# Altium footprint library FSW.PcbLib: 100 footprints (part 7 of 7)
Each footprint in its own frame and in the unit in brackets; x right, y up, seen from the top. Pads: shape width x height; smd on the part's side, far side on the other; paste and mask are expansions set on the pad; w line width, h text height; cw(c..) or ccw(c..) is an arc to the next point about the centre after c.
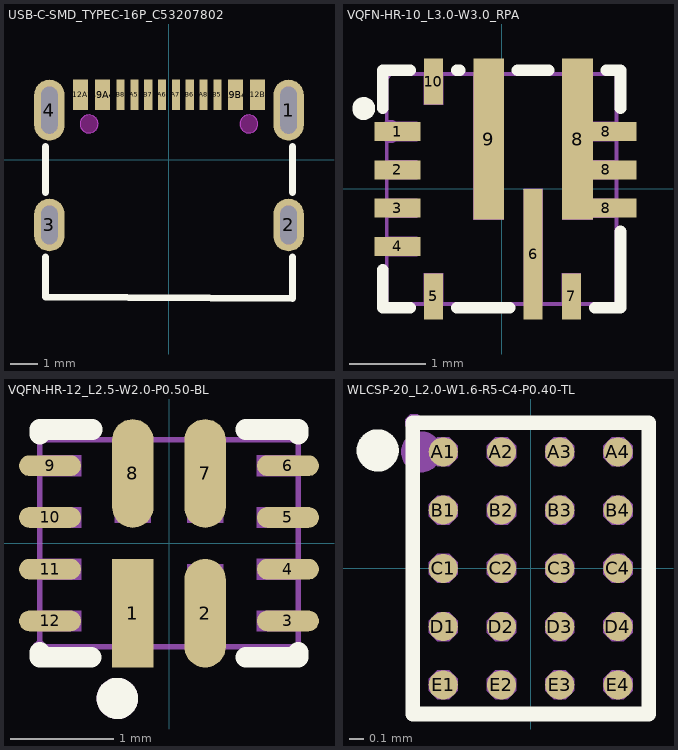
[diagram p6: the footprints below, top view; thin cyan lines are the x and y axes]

## USB-C-SMD_TYPEC-16P_C53207802 [mm]
pads (16):
  oval 1.1x2.2 hole 0.6 slot 1.7 at 90 deg copper offset 0,0 paste-2539.97 mask+0.05: 1(4.32,1.8)
  oval 1.1x1.9 hole 0.6 slot 1.4 at 90 deg copper offset 0,0 paste-2539.97 mask+0.05: 2(4.32,-2.35)
  oval 1.1x1.9 hole 0.6 slot 1.4 at 90 deg paste-2539.97 mask+0.05: 3(-4.32,-2.35)
  oval 1.1x2.2 hole 0.6 slot 1.7 at 90 deg paste-2539.97 mask+0.05: 4(-4.32,1.8)
  rect 0.3x1.1 smd paste+0 mask+0.05: A5(-1.25,2.35) A6(-0.25,2.35) A7(0.25,2.35) A8(1.25,2.35) B5(1.75,2.35) B6(0.75,2.35) B7(-0.75,2.35) B8(-1.75,2.35)
  rect 0.55x1.1 smd paste+0 mask+0.05: A9B4(2.4,2.35) A12B1(3.2,2.35) B9A4(-2.4,2.35) B12A1(-3.2,2.35)
Top Overlay:
  lines w0.254: -4.47,-3.517 -4.47,-4.951 4.47,-5.001 4.47,-3.517 ; -4.47,-1.183 -4.47,0.484 ; 4.47,-1.183 4.47,0.484
Keep-Out Layer:
  board cut-out: 3.215,1.3 3.215,1.235 3.166,1.116 3.074,1.024 2.955,0.975 2.825,0.975 2.706,1.024 2.615,1.116 2.565,1.235 2.565,1.3 2.565,1.365 2.615,1.484 2.706,1.575 2.825,1.625 2.955,1.625 3.074,1.575 3.166,1.484 3.215,1.365 3.215,1.3
  board cut-out: -2.565,1.3 -2.565,1.235 -2.614,1.116 -2.706,1.024 -2.825,0.975 -2.955,0.975 -3.074,1.024 -3.165,1.116 -3.215,1.235 -3.215,1.3 -3.215,1.365 -3.165,1.484 -3.074,1.575 -2.955,1.625 -2.825,1.625 -2.706,1.575 -2.614,1.484 -2.565,1.365 -2.565,1.3
Keep-Out Layer:
  circle w0.003: c2.89,1.3 r0.325
  circle w0.003: c-2.89,1.3 r0.325
  region: 3.215,1.3 3.206,1.222 3.178,1.149 3.133,1.084 3.075,1.032 3.005,0.996 2.929,0.977 2.851,0.977 2.775,0.996 2.706,1.032 2.647,1.084 2.602,1.149 2.575,1.222 2.565,1.3 2.575,1.378 2.602,1.451 2.647,1.515 2.706,1.567 2.775,1.604 2.851,1.623 2.929,1.623 3.005,1.604 3.075,1.567 3.133,1.515 3.178,1.451 3.206,1.378
  region: 3.215,1.3 3.215,1.235 3.166,1.116 3.074,1.024 2.955,0.975 2.825,0.975 2.706,1.024 2.615,1.116 2.565,1.235 2.565,1.3 2.565,1.365 2.615,1.484 2.706,1.575 2.825,1.625 2.955,1.625 3.074,1.575 3.166,1.484 3.215,1.365 3.215,1.3
  region: -2.565,1.3 -2.574,1.222 -2.602,1.149 -2.647,1.084 -2.705,1.032 -2.775,0.996 -2.851,0.977 -2.929,0.977 -3.005,0.996 -3.075,1.032 -3.133,1.084 -3.178,1.149 -3.205,1.222 -3.215,1.3 -3.205,1.378 -3.178,1.451 -3.133,1.515 -3.075,1.567 -3.005,1.604 -2.929,1.623 -2.851,1.623 -2.775,1.604 -2.705,1.567 -2.647,1.515 -2.602,1.451 -2.574,1.378
  region: -2.565,1.3 -2.565,1.235 -2.614,1.116 -2.706,1.024 -2.825,0.975 -2.955,0.975 -3.074,1.024 -3.165,1.116 -3.215,1.235 -3.215,1.3 -3.215,1.365 -3.165,1.484 -3.074,1.575 -2.955,1.625 -2.825,1.625 -2.706,1.575 -2.614,1.484 -2.565,1.365 -2.565,1.3
Mechanical 1:
  circle w0.003: c2.89,1.3 r0.325
  circle w0.003: c-2.89,1.3 r0.325
3D body "USB-C-SMD_TYPE-C-16PIN-2MD-073.step": height 3.36, standoff -0.8, extent -4.343,-4.935 4.597,2.645

## VQFN-HR-10_L3.0-W3.0_RPA [mm]
pads (13):
  rect 0.6x0.25 smd paste-100 mask+0.05: 1(-1.36,0.75) 2(-1.36,0.25) 3(-1.36,-0.25) 4(-1.36,-0.75)
  rect 0.25x0.6 smd paste-100 mask+0.05: 5(-0.89,-1.4) 7(0.91,-1.4) 10(-0.89,1.4)
  rect 0.25x1.7 smd paste-100 mask+0.05: 6(0.41,-0.85)
  rect 0.4x2.1 smd paste-100 mask+0.05: 8(0.99,0.65) 9(-0.17,0.65)
  rect 0.8x0.25 smd paste-100 mask+0.05: 8(1.36,-0.25) 8(1.36,0.25) 8(1.36,0.75)
Top Overlay:
  circle w0.15: c-1.8,1.05 r0.075
  lines w0.152: -1.55,-1.055 -1.55,-1.55 -1.195,-1.55 ; -1.55,1.055 -1.55,1.55 -1.195,1.55 ; -0.585,-1.55 0.105,-1.55 ; -0.585,1.55 -0.547,1.55 ; 0.207,1.55 0.613,1.55 ; 1.215,-1.55 1.55,-1.55 1.55,-0.555 ; 1.367,1.55 1.55,1.55 1.55,1.055
Top Paste:
  region: 0.285,-1.699 0.535,-1.699 0.535,0 0.285,0 0.285,-0.699
  region: -0.765,1.7 -1.015,1.7 -1.015,1.1 -0.765,1.1 -0.765,1.177
  region: -1.06,0.625 -1.06,0.875 -1.66,0.875 -1.66,0.625 -1.583,0.625
  region: -1.06,0.125 -1.06,0.375 -1.66,0.375 -1.66,0.125 -1.583,0.125
  region: -1.06,-0.375 -1.06,-0.125 -1.66,-0.125 -1.66,-0.375 -1.583,-0.375
  region: -1.06,-0.875 -1.06,-0.625 -1.66,-0.625 -1.66,-0.875 -1.583,-0.875
  region: -1.015,-1.7 -0.765,-1.7 -0.765,-1.1 -1.015,-1.1 -1.015,-1.177
  region: 0.785,-1.7 1.035,-1.7 1.035,-1.1 0.785,-1.1 0.785,-1.177
  region: 0.03,1.7 -0.37,1.7 -0.37,-0.4 0.03,-0.4 0.03,-0.337
  region: 1.19,1.7 0.79,1.7 0.79,-0.4 1.19,-0.4 1.19,-0.375 1.76,-0.375 1.76,-0.126 1.19,-0.126 1.19,0.125 1.76,0.125 1.76,0.375 1.19,0.375 1.19,0.625 1.76,0.625 1.76,0.875 1.19,0.875 1.19,1.455
Mechanical 2:
  circle w0.15: c-1.45,0.75 r0.075
Mechanical 6:
  lines w0.051: -1.5,-1.5 1.5,-1.5 1.5,1.5 -1.5,1.5 -1.5,-1.5
Mechanical 8:
  region: -1.44,1.5 -1.44,1.475 -1.475,1.44 -1.525,1.44 -1.56,1.475 -1.56,1.5 -1.56,1.525 -1.525,1.56 -1.475,1.56 -1.44,1.525 -1.44,1.5
Mechanical 9:
  region: -1.015,1.1 -1.015,1.5 -0.765,1.5 -0.765,1.1
  region: -1.1,-0.875 -1.5,-0.875 -1.5,-0.625 -1.1,-0.625
  region: -1.5,0.875 -1.1,0.875 -1.1,0.625 -1.5,0.625
  region: -1.5,0.375 -1.1,0.375 -1.1,0.125 -1.5,0.125
  region: -1.5,-0.125 -1.1,-0.125 -1.1,-0.375 -1.5,-0.375
  region: -1.015,-1.5 -1.015,-1.1 -0.765,-1.1 -0.765,-1.5
  region: 0.785,-1.5 0.785,-1.1 1.035,-1.1 1.035,-1.5
  region: 0.285,0 0.535,0 0.535,-1.5 0.285,-1.5
  region: 0.79,1.5 1.19,1.5 1.19,-0.4 0.79,-0.4
  region: 1.1,-0.125 1.5,-0.125 1.5,-0.375 1.1,-0.375
  region: 1.1,0.375 1.5,0.375 1.5,0.125 1.1,0.125
  region: 1.1,0.875 1.5,0.875 1.5,0.625 1.1,0.625
  region: -0.37,1.5 0.03,1.5 0.03,-0.4 -0.37,-0.4

## VQFN-HR-12_L2.5-W2.0-P0.50-BL [mm]
pads (12):
  rect 0.4x1.05 smd: 1(-0.35,-0.675)
  oval 0.4x1.05 smd: 2(0.35,-0.675) 7(0.35,0.675) 8(-0.35,0.675)
  oval 0.6x0.2 smd: 3(1.15,-0.75) 4(1.15,-0.25) 5(1.15,0.25) 6(1.15,0.75) 9(-1.15,0.75) 10(-1.15,0.25) 11(-1.15,-0.25) 12(-1.15,-0.75)
Top Overlay:
  circle w0.2: c-0.5,-1.5 r0.1
  lines w0.2: -1.25,-1.054 -1.25,-1.1 -0.754,-1.1 ; -1.25,1.054 -1.25,1.1 -0.742,1.1 ; 0.741,-1.1 1.25,-1.1 1.25,-1.054 ; 0.741,1.1 1.25,1.1 1.25,1.054
Mechanical 2:
  circle w0.2: c-0.5,-1.5 r0.1
Mechanical 6:
  lines w0.051: -1.25,-1 -1.25,1 1.25,1 1.25,-0.94 1.25,-1 -1.25,-1
Mechanical 8:
  region: -1.19,-1 -1.19,-1.025 -1.225,-1.06 -1.275,-1.06 -1.31,-1.025 -1.31,-1 -1.31,-0.975 -1.275,-0.94 -1.225,-0.94 -1.19,-0.975 -1.19,-1
Mechanical 9:
  region: 0.175,0.2 0.175,1 0.525,1 0.525,0.2
  region: -0.525,0.2 -0.525,1 -0.175,1 -0.175,0.2
  region: -0.525,-1 -0.525,-0.2 -0.175,-0.2 -0.175,-1
  region: 0.175,-1 0.175,-0.2 0.525,-0.2 0.525,-1
  region: 0.85,0.85 1.25,0.85 1.25,0.65 0.85,0.65
  region: 0.85,0.35 1.25,0.35 1.25,0.15 0.85,0.15
  region: 0.85,-0.15 1.25,-0.15 1.25,-0.35 0.85,-0.35
  region: 0.85,-0.65 1.25,-0.65 1.25,-0.85 0.85,-0.85
  region: -1.25,-0.65 -0.85,-0.65 -0.85,-0.85 -1.25,-0.85
  region: -1.25,-0.15 -0.85,-0.15 -0.85,-0.35 -1.25,-0.35
  region: -1.25,0.35 -0.85,0.35 -0.85,0.15 -1.25,0.15
  region: -1.25,0.85 -0.85,0.85 -0.85,0.65 -1.25,0.65

## WLCSP-20_L2.0-W1.6-R5-C4-P0.40-TL [mm]
pads (20):
  round 0.2 smd paste-100 mask+0.05: A1(-0.6,0.8) A2(-0.2,0.8) A3(0.2,0.8) A4(0.6,0.8) B1(-0.6,0.4) B2(-0.2,0.4) B3(0.2,0.4) B4(0.6,0.4) C1(-0.6,0) C2(-0.2,0) C3(0.2,0) C4(0.6,0) D1(-0.6,-0.4) D2(-0.2,-0.4) D3(0.2,-0.4) D4(0.6,-0.4) E1(-0.6,-0.8) E2(-0.2,-0.8) E3(0.2,-0.8) E4(0.6,-0.8)
Top Overlay:
  circle w0.15: c-1.05,0.81 r0.07
  lines w0.1: -0.804,-1 -0.81,-1 ; -0.804,1 -0.81,1 ; 0.804,-1 0.81,-1 ; 0.804,1 0.81,1 ; -0.81,-1 0.81,-1 ; -0.81,-1 -0.81,1 ; -0.81,1 0.81,1 ; 0.81,-1 0.81,1
Top Paste:
  drawing of 20 lines, arcs and shapes, not listed
Mechanical 2:
  circle w0.14: c-0.75,0.8 r0.07
Mechanical 6:
  lines w0.051: -0.8,-1 -0.8,1 0.8,1 0.8,-1 -0.8,-1
Mechanical 8:
  region: -0.74,1 -0.74,0.975 -0.775,0.94 -0.825,0.94 -0.86,0.975 -0.86,1 -0.86,1.025 -0.825,1.06 -0.775,1.06 -0.74,1.025 -0.74,1
Mechanical 9:
  drawing of 20 lines, arcs and shapes, not listed
3D body "WLCSP-20_L2.0-W1.6-R5-C4-P0.40-TL.step": height 0.6, standoff 0, extent -0.807,-1.008 0.807,1.008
